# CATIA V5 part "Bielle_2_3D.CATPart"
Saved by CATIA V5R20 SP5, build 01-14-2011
Part number: Bielle_2_3D
Bounding box of the stored display mesh (mm): x 72 to 144, y -10.808 to 390.741, z -418.088 to -74.037
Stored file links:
  J:\Thinkmotion\Projet IAO\A envoyer\Bielle_2_3D.CATPart
  J:\Thinkmotion\Projet IAO\A modifier\Bielle_1.CATPart
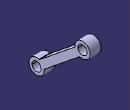
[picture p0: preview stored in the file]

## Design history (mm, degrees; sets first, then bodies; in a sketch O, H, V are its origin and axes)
Body1 (main body)
  DatumSurface1
  Line1 to Line5: stored without definition
  Sketch1 on face of DatumSurface1, origin (72, 0, 0), H (0, 1, 0), V (0, 0, 1)
    line L1 (57.1075, -321.4161) -> (291.3724, -131.8412)
    point P2 (291.3724, -131.8412)
    line L2 (88.5606, -360.2839) -> (322.8254, -170.709)
    point P3 (88.5606, -360.2839)
    point P4 (322.8254, -170.709)
    arc A1 centre (39.1735, -368.0891) radius 50 from (57.1075, -321.4161) to (88.5606, -360.2839) ccw
    point P5 (39.1735, -368.0891)
    point P6 (88.5606, -360.2839)
    circle A2 centre (39.1735, -368.0891) radius 30
    circle A3 centre (340.7594, -124.0359) radius 30
    point P7 (340.7594, -124.0359)
    arc A4 centre (340.7594, -124.0359) radius 50 from (322.8254, -170.709) to (291.3724, -131.8412) ccw
    point P8 (322.8254, -170.709)
    point P9 (291.3724, -131.8412)
    reference projected point E1 (39.1735, -368.0891) from Line1
    reference projected point E2 (340.7594, -124.0359) from Line2
    reference projected point E3 (39.1735, -368.0891) from Line3
    reference projected line E4 (39.1735, -368.0891) -> (340.7594, -124.0359) from Line4
    reference projected line E5 (39.1735, -368.0891) -> (340.7594, -124.0359) from Line5
    radius A2 = 30
    radius A1 = 50
    radius A4 = 50
    radius A3 = 30
    distance L1 L2 = 50
    distance L1 E5 = 25
    coincidence: P6 L2, P6 P3, P8 P4, P9 P2, P5 E1, P7 E2, P5 E3
    parallelism: E4 L1
  Pad1: profile Sketch1, direction (1, 0, 0), length 72
  Fillet1: radius 5, on edge [face of Pad1 from Sketch1.A1 | face of Pad1 from Sketch1.L1]; edge [face of Pad1 from Sketch1.L1 | face of Pad1 from Sketch1.A4]; edge [face of Pad1 from Sketch1.L2 | face of Pad1 from Sketch1.A1]; edge [face of Pad1 from Sketch1.A4 | face of Pad1 from Sketch1.L2]
  Sketch2 on start face of Pad1, origin (72, 0, 0), H (0, 1, 0), V (0, 0, 1)
    line L1 (57.1075, -321.4161) -> (291.3724, -131.8412)
    point P2 (291.3724, -131.8412)
    line L2 (88.5606, -360.2839) -> (322.8254, -170.709)
    point P3 (88.5606, -360.2839)
    point P4 (322.8254, -170.709)
    arc A1 centre (39.1735, -368.0891) radius 50 from (57.1075, -321.4161) to (88.5606, -360.2839) ccw
    point P5 (39.1735, -368.0891)
    point P6 (88.5606, -360.2839)
    circle A2 centre (39.1735, -368.0891) radius 30
    circle A3 centre (340.7594, -124.0359) radius 30
    point P7 (340.7594, -124.0359)
    arc A4 centre (340.7594, -124.0359) radius 50 from (322.8254, -170.709) to (291.3724, -131.8412) ccw
    point P8 (322.8254, -170.709)
    point P9 (291.3724, -131.8412)
    reference projected point E1 (39.1735, -368.0891) from Line1
    reference projected point E2 (340.7594, -124.0359) from Line2
    reference projected point E3 (39.1735, -368.0891) from Line3
    reference projected line E4 (39.1735, -368.0891) -> (340.7594, -124.0359) from Line4
    reference projected line E5 (39.1735, -368.0891) -> (340.7594, -124.0359) from Line5
    radius A2 = 30
    radius A1 = 50
    radius A4 = 50
    radius A3 = 30
    distance L1 L2 = 50
    distance L1 E5 = 25
    coincidence: P6 L2, P6 P3, P8 P4, P9 P2, P5 E1, P7 E2, P5 E3
    parallelism: E4 L1
  Pad2: profile Sketch2, direction (1, 0, 0), length 72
